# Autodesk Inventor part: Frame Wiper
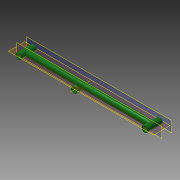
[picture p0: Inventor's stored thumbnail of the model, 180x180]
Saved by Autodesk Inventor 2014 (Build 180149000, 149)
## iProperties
Created: 2006-03
Part Number: Frame Wiper
Document SubType Name: Modeling
Designer: Autodesk, Inc.
Material: Stainless Steel, 440C
Mass: 450.336 g
Surface Area: 586.145 cm^2
Volume: 58.1078 cm^3
Density: 7.75 g/cm^3
Appearance: Smooth - Dark Forest Green
Author: Autodesk, Inc.
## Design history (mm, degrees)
sketch "Sketch1"
  geometry: L1 (0, -28.185)-(0, 16.364) reference; L2 (-305.6, 0)-(307.6, 0) reference; C1 r 10 at (210, 0); 1 further point
  constraints: 1 centre point
  dimensions: "d3" = 20 diameter of C1; "d6" = 210 distance of C1.centre point (0, 0)
extrude "Extrusion1" new body sketch "Sketch1" stored distance "d4" = 50; taper "d5" = 0 deg
sketch "Sketch3"
  geometry: C1 r 10 at (0, 0); 1 further point
  constraints: 1 centre point, 1 coincident
  dimensions: "d8" = 20 diameter of C1
extrude "Extrusion2" join sketch "Sketch3" stored distance "d9" = 50; taper "d10" = 0 deg
mirror "Mirror1"
shell "Shell1" dims "d11" = 2
sketch "Sketch4"
  geometry: C1 r 10 at (32.287, -11.821); A1 r 8 centre (-210, 0) between (-210, -8) and (-210, 8) reference; 1 further point
  constraints: 1 centre point
  dimensions: "d13" = 242.575 distance of C1.centre A1.centre; "d14" = 20 diameter of C1; "d21" = 11.821 vertical distance of point (0, 0) C1.centre
workaxis "Work Axis1"
node "Ref"
sketch "Sketch5"
  geometry: C1 r 8 at (210, 0) reference; C2 r 8 at (-210, 0) reference; 1 further point
node "Bearing"
node "Ref_Wiper"
workaxis "Work Axis2"
sketch "Sketch6"
  geometry: C1 r 10 at (32.287, -11.821); C2 r 8 at (32.287, -11.821); 1 further point
  constraints: 2 centre point
  dimensions: "d24" = 20 diameter of C1; "d25" = 32.2868 horizontal distance of point (0, 0) C1.centre (derived); "d26" = 11.821 vertical distance of C1.centre point (0, 0) (derived); "d27" = 16 diameter of C2 (computed from d24)
extrude "Extrusion3" join sketch "Sketch6" distance "d22" = 18; taper "d23" = 0 deg
body "Solid1"
other parameters: "d16" = 0, "d20" = 8
